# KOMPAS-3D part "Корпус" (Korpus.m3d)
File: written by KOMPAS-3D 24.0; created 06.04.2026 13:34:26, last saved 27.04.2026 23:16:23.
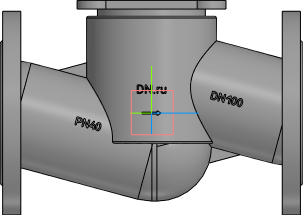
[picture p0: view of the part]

Document properties: Автор: R2D2; Полное имя файла: C:\Работа\ГОТОВЫЕ ИСХОДНИКИ\VSO2130M-F-S Клапан запорный сальниковый DN.ru Ду15-100 Ру40\исходные материалы\DN100\Korpus.m3d

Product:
- Body: Труба / Нестандартная труба / L = 226 мм  | qty 1  | 2 such rows
    Материал: Нестандартная труба (density 7856 kg/m3)
    Масса: 55.375725
    Раздел спецификации: Детали
    Примечание: 20,08 кг
    additional columns: Pipeline; 0.12; 0; 0; 0.002; 0.22598; true; 0.04
- Body: Тело 4  | qty 1
    Материал: Нестандартная труба (density 7856 kg/m3)
    Масса: 55.375725
- Body: Тело 5  | qty 1
    Материал: Нестандартная труба (density 7856 kg/m3)
    Масса: 55.375725
- Body: Тело 8  | qty 1
    Материал: Нестандартная труба (density 7856 kg/m3)
    Масса: 55.375725
- Body: Тело 10  | qty 1
    Материал: Нестандартная труба (density 7856 kg/m3)
    Масса: 55.375725
- Body: Тело 11  | qty 1
    Материал: Нестандартная труба (density 7856 kg/m3)
    Масса: 55.375725
- Body: Тело 12  | qty 1
    Материал: Нестандартная труба (density 7856 kg/m3)
    Масса: 55.375725
- Body: Тело 13  | qty 1
    Материал: Нестандартная труба (density 7856 kg/m3)
    Масса: 55.375725
- Body: Тело 14  | qty 1
    Материал: Нестандартная труба (density 7856 kg/m3)
    Масса: 55.375725
- Body: Тело 15  | qty 1
    Материал: Нестандартная труба (density 7856 kg/m3)
    Масса: 55.375725
- Part/product: Корпус
    Масса: 6.9

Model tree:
1. Труба:1  (labels: {F703FF30-5BE6-4673-A7F1-8EDA1BE1E2D1}; SHAPEOBJECT3D_ATTR_BUTT; SHAPEOBJECT3D_ATTR_VALID; SHAPEOBJECT3D_ATTR_BUTT_AREA)
     PIPE_R = 3
2. Труба:2  (labels: {F703FF30-5BE6-4673-A7F1-8EDA1BE1E2D1}; SHAPEOBJECT3D_ATTR_BUTT; SHAPEOBJECT3D_ATTR_VALID; SHAPEOBJECT3D_ATTR_BUTT_AREA)
     PIPE_R = 3
3. Колонна
4. Элемент выдавливания:1
     Смещение 1 = -1; Смещение 2 = -5
5. Скругление:17  (with: Ребро.Элемент выдавливания:1)
     Радиус = 2
6. Скругление:18  (with: Ребро.Элемент выдавливания:1)
7. Скругление:24
     Радиус = 1.5
8. Элемент выдавливания:2
     Расстояние 1 = 6
9. Эскиз:4  (with: Грань.Элемент выдавливания:1)
10. Элемент выдавливания:3
     Расстояние 1 = 8.33333
11. ОТЛИВКА
12. Скругление:6  (with: Грань.Элемент выдавливания:1)
     Радиус = 2
13. Элемент выдавливания:6  (with: Грань.Элемент выдавливания:1)
     Смещение 1 = 4
14. ЛЕЙБЛ
15. Элемент выдавливания:7  (with: Грань.Элемент выдавливания:1)
     Расстояние 1 = 75.974; Смещение 1 = 1
16. Dn
17. Pn
18. Стрелочка
19. Элемент выдавливания:10  (with: Грань.Труба:1)
     Расстояние 1 = 60.9678; Смещение 1 = 1
20. Элемент выдавливания:11  (with: Грань.Труба:2)
     Расстояние 1 = 60.2713; Смещение 1 = 1
21. Элемент выдавливания:12  (with: Грань.Элемент выдавливания:1)
     Расстояние 1 = 75.9998; Смещение 1 = 1
22. Материал
23. Элемент выдавливания:13  (with: Грань.Элемент выдавливания:1)
     Расстояние 1 = 75.4928; Смещение 1 = 0.5
24. Фланец верх  (with: Грань.Элемент выдавливания:3)
25. Элемент выдавливания:14
     Расстояние 1 = 10
26. Эскиз:18  (with: Грань.Элемент выдавливания:14)
27. Элемент выдавливания:15
     Расстояние 1 = 0.5
28. Эскиз:19  (with: Грань.Элемент выдавливания:14, Ребро.Элемент выдавливания:14)
29. Элемент выдавливания:16  (with: Грань.Элемент выдавливания:14)
     Расстояние 1 = 0.5; Расстояние 2 = 11; Смещение 2 = 1
30. Фланец
31. Элемент вращения:1
     Угол 1 = 360
32. отвертие во фланце  (with: Грань.Элемент вращения:1)
33. Элемент выдавливания:8
34. Массив по концентрической сетке:2  (with: Элемент выдавливания:8, Эскиз:10, Грань.Элемент вращения:1)  (8 pattern instances)
     Шаг 2 = 360
35. Зеркальный массив:1
36. Экземпляр ( 1 )
37. Экземпляр ( 2 )  (with: Элемент вращения:1, Массив по концентрической сетке:2, Экземпляр ( 1 ), Элемент выдавливания:8)
38. Экземпляр ( 3 )  (with: Элемент выдавливания:8)
39. Экземпляр ( 4 )  (with: Элемент выдавливания:8)
40. Экземпляр ( 5 )  (with: Элемент выдавливания:8)
41. Экземпляр ( 6 )  (with: Элемент выдавливания:8)
42. Экземпляр ( 7 )  (with: Элемент выдавливания:8)
43. Экземпляр ( 8 )  (with: Элемент выдавливания:8)
44. Массив по концентрической сетке:3  (with: Элемент выдавливания:16, Эскиз:19)  (labels: Клапан запорный DN.ru Ду100 Ру40)  (4 pattern instances)
     Шаг 2 = 360
45. Скругление:25  (with: Ребро.Элемент выдавливания:1)
     Радиус = 2

Expressions: DS/2+3; LL/2; DN/2; A/3+DN; D1/2+25; D2/2-15
Referenced files in C:\Работа\ГОТОВЫЕ ИСХОДНИКИ\VSO2130M-F-S Клапан запорный сальниковый DN.ru Ду15-100 Ру40\исходные материалы\DN100\: VSO2130M-F-S Клапан запорный DN.ru Ду100 Ру40.a3d
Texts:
  GOST 26.020 Pr3
  var3D
  GS-C25
  смещение колонны вниз
  LL-10
  DN+20
  DS+25
  Труба / Нестандартная труба / L = %s мм
  Ось Y.Начало координат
